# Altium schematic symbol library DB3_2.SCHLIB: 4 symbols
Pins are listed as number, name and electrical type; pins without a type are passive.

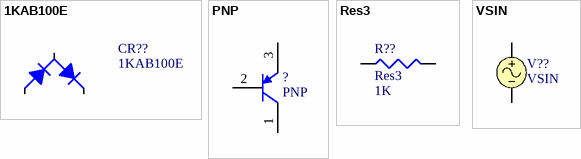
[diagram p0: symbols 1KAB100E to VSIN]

## 1KAB100E
designator CR??
1.2 Amp Rectifier Bridge
footprint D-38 (Footprint not found)
footprint SOT-23_N (SOT23, 3-Leads, Body 2.9x1.3mm, Pitch 0.95mm, Lead Span 2.5mm, IPC Medium Density)
pins: 1 2, 2 1, 3

## PNP
designator ?
PNP Bipolar Transistor
footprint SOT-23B_N (SOT23, 3-Leads, Body 2.9x1.3mm, Pitch 0.95mm, Lead Span 2.4mm, IPC Medium Density)
footprint SOT-23B_L (SOT23, 3-Leads, Body 2.9x1.3mm, Pitch 0.95mm, Lead Span 2.4mm, IPC High Density)
footprint SOT-23B_M (SOT23, 3-Leads, Body 2.9x1.3mm, Pitch 0.95mm, Lead Span 2.4mm, IPC Low Density)
simulation model PNP
signal-integrity model PNP
pins: 1 C, 2 B, 3 E

## Res3
designator R??  value 1K
Resistor
footprint J1-0603 (Chip Resistor, Body 1.6x0.8mm, IPC High Density)
footprint 14-1210 (Chip Resistor, Body 3.2x2.5mm, IPC High Density)
footprint 12Z-2010 (Chip Resistor, Body 5.0x2.5mm, IPC High Density)
footprint RESC6332 (Chip Resistor, Body 6.3x3.2mm, IPC High Density)
simulation model RESISTOR (Resistor)
signal-integrity model Res
pins: 1, 2

## VSIN
designator V??
Sinusoidal Voltage Source; Note: PCB Footprint - Not required
simulation model VSIN
pins: 1, 2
